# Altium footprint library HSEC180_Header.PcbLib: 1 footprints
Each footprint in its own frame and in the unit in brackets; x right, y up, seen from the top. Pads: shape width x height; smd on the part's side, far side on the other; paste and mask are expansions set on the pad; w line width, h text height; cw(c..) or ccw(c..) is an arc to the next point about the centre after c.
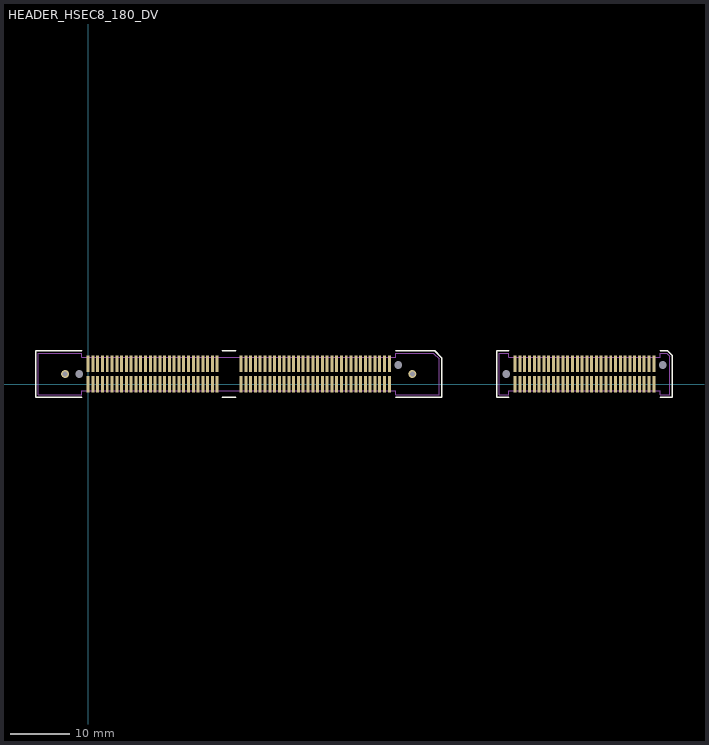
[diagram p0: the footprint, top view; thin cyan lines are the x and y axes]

## HEADER_HSEC8_180_DV [mm]
pads (186):
  rect 0.5x2.724 smd mask+0.076: 1(0,0) 2(0,3.4) 3(0.8,0) 4(0.8,3.4) 5(1.6,0) 6(1.6,3.4) 7(2.4,0) 8(2.4,3.4) 9(3.2,0) 10(3.2,3.4) 11(4,0) 12(4,3.4) 13(4.8,0) 14(4.8,3.4) 15(5.6,0) 16(5.6,3.4) 17(6.4,0) 18(6.4,3.4) 19(7.2,0) 20(7.2,3.4) 21(8,0) 22(8,3.4) 23(8.8,0) 24(8.8,3.4) 25(9.6,0) 26(9.6,3.4) 27(10.4,0) 28(10.4,3.4) 29(11.2,0) 30(11.2,3.4) 31(12,0) 32(12,3.4) 33(12.8,0) 34(12.8,3.4) 35(13.6,0) 36(13.6,3.4) 37(14.4,0) 38(14.4,3.4) 39(15.2,0) 40(15.2,3.4) 41(16,0) 42(16,3.4) 43(16.8,0) 44(16.8,3.4) 45(17.6,0) 46(17.6,3.4) 47(18.4,0) 48(18.4,3.4) 49(19.2,0) 50(19.2,3.4) 51(20,0) 52(20,3.4) 53(20.8,0) 54(20.8,3.4) 55(21.6,0) 56(21.6,3.4) 57(25.6,0) 58(25.6,3.4) 59(26.4,0) 60(26.4,3.4) 61(27.2,0) 62(27.2,3.4) 63(28,0) 64(28,3.4) 65(28.8,0) 66(28.8,3.4) 67(29.6,0) 68(29.6,3.4) 69(30.4,0) 70(30.4,3.4) 71(31.2,0) 72(31.2,3.4) 73(32,0) 74(32,3.4) 75(32.8,0) 76(32.8,3.4) 77(33.6,0) 78(33.6,3.4) 79(34.4,0) 80(34.4,3.4) 81(35.2,0) 82(35.2,3.4) 83(36,0) 84(36,3.4) 85(36.8,0) 86(36.8,3.4) 87(37.6,0) 88(37.6,3.4) 89(38.4,0) 90(38.4,3.4) 91(39.2,0) 92(39.2,3.4) 93(40,0) 94(40,3.4) 95(40.8,0) 96(40.8,3.4) 97(41.6,0) 98(41.6,3.4) 99(42.4,0) 100(42.4,3.4) 101(43.2,0) 102(43.2,3.4) 103(44,0) 104(44,3.4) 105(44.8,0) 106(44.8,3.4) 107(45.6,0) 108(45.6,3.4) 109(46.4,0) 110(46.4,3.4) 111(47.2,0) 112(47.2,3.4) 113(48,0) 114(48,3.4) 115(48.8,0) 116(48.8,3.4) 117(49.6,0) 118(49.6,3.4) 119(50.4,0) 120(50.4,3.4) 121(71.468,0) 122(71.468,3.4) 123(72.268,0) 124(72.268,3.4) 125(73.068,0) 126(73.068,3.4) 127(73.868,0) 128(73.868,3.4) 129(74.668,0) 130(74.668,3.4) 131(75.468,0) 132(75.468,3.4) 133(76.268,0) 134(76.268,3.4) 135(77.068,0) 136(77.068,3.4) 137(77.868,0) 138(77.868,3.4) 139(78.668,0) 140(78.668,3.4) 141(79.468,0) 142(79.468,3.4) 143(80.268,0) 144(80.268,3.4) 145(81.068,0) 146(81.068,3.4) 147(81.868,0) 148(81.868,3.4) 149(82.668,0) 150(82.668,3.4) 151(83.468,0) 152(83.468,3.4) 153(84.268,0) 154(84.268,3.4) 155(85.068,0) 156(85.068,3.4) 157(85.868,0) 158(85.868,3.4) 159(86.668,0) 160(86.668,3.4) 161(87.468,0) 162(87.468,3.4) 163(88.268,0) 164(88.268,3.4) 165(89.068,0) 166(89.068,3.4) 167(89.868,0) 168(89.868,3.4) 169(90.668,0) 170(90.668,3.4) 171(91.468,0) 172(91.468,3.4) 173(92.268,0) 174(92.268,3.4) 175(93.068,0) 176(93.068,3.4) 177(93.868,0) 178(93.868,3.4) 179(94.668,0) 180(94.668,3.4)
  round 0.025 hole 1.27 unplated mask+0.876: 181(-1.5,1.7) 182(51.9,3.2) 183(69.968,1.7) 184(96.168,3.2)
  round 1.348 hole 0.84: 185(-3.85,1.7) 186(54.25,1.7)
Top Overlay:
  lines w0.254: -1.1,-2.181 -8.756,-2.181 -8.756,5.581 -1.1,5.581 ; 22.481,-2.181 24.719,-2.181 ; 22.481,5.581 24.719,5.581 ; 51.5,-2.181 59.156,-2.181 59.156,4.438 58.013,5.581 51.5,5.581 ; 70.368,-2.181 68.387,-2.181 68.387,5.581 70.368,5.581 ; 95.733,-2.181 97.749,-2.181 97.749,4.819 96.987,5.581 95.758,5.581
Mechanical 1:
  lines w0.025: -8.375,-1.8 -1.1,-1.8 -1.1,-1.1 51.5,-1.1 51.5,-1.8 58.775,-1.8 58.775,4.225 57.8,5.2 51.5,5.2 51.5,4.5 -1.1,4.5 -1.1,5.2 -8.375,5.2 -8.375,-1.8 ; 68.768,-1.768 68.8,-1.8 70.368,-1.8 70.368,-1.1 95.768,-1.1 95.768,-1.8 97.368,-1.8 97.368,4.632 96.8,5.2 95.768,5.2 95.768,4.5 70.368,4.5 70.368,5.2 68.768,5.2 68.768,-1.768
